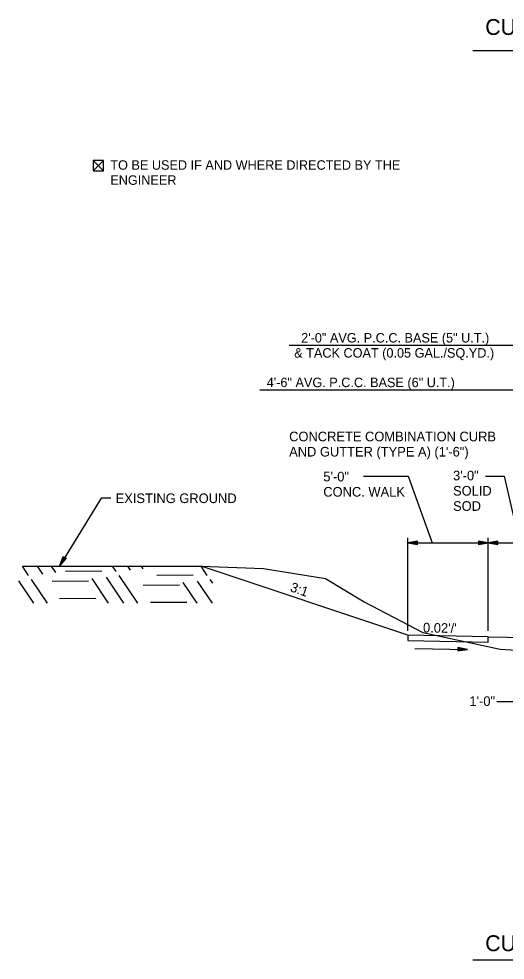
# Model space of a CAD drawing. Extents: x 1001270 to 1003428, y 1840152 to 1842912.
# Drawn here: x 1001294.8 to 1001325.1, y 1841273 to 1841331.7 of the extents above; entities that cross this region are included whole.
import ezdxf

# ---------------------------------------------------------------- set-up
doc = ezdxf.new("R2010")
doc.units = 0
for name, color, linetype in [('10', 7, 'Continuous'), ('19', 7, 'Continuous'), ('20', 7, 'Continuous'), ('8', 7, 'Continuous'), ('Default', 7, 'Continuous')]:
    doc.layers.add(name, color=color, linetype=linetype)

# ---------------------------------------------------------------- blocks, each defined once
blk = doc.blocks.new('TM')
at = {"layer": '8'}
for p, q in [((-120.309, 21.181), (-119.787, -20.829)), ((0, 0), (-120.309, 21.181)), ((-31.382, 2.945), (-120.176, 10.512)), ((-119.787, -20.829), (0, 0)), ((-119.911, -10.826), (-31.307, -3.057))]:
    blk.add_line(p, q, dxfattribs=at)

msp = doc.modelspace()

# ---------------------------------------------------------------- linework, layer by layer
at = {"layer": '10'}
for p, q in [((1001299.414, 1841322.865), (1001300.055, 1841322.224)), ((1001300.055, 1841322.865), (1001299.414, 1841322.224)), ((1001299.795, 1841322.224), (1001299.806, 1841322.224))]:
    msp.add_line(p, q, dxfattribs=at)
msp.add_lwpolyline([(1001299.806, 1841322.224), (1001300.055, 1841322.224), (1001300.055, 1841322.865), (1001299.414, 1841322.865), (1001299.414, 1841322.224), (1001299.795, 1841322.224)], dxfattribs=at)
at = {"layer": '19'}
for p, q in [((1001359.207, 1841329.7), (1001323.061, 1841329.7)), ((1001328.517, 1841311.347), (1001311.62, 1841311.347)), ((1001326.017, 1841308.547), (1001309.801, 1841308.547)), ((1001316.248, 1841303.201), (1001319.04, 1841303.201)), ((1001319.04, 1841303.201), (1001320.535, 1841299.044)), ((1001323.844, 1841303.201), (1001325.022, 1841303.201)), ((1001325.022, 1841303.201), (1001325.979, 1841299.044)), ((1001319.017, 1841293.556), (1001319.017, 1841299.344)), ((1001319.617, 1841299.149), (1001319.017, 1841299.044)), ((1001319.017, 1841299.044), (1001328.517, 1841299.044)), ((1001319.017, 1841299.044), (1001319.617, 1841298.939)), ((1001319.617, 1841299.094), (1001319.177, 1841299.059)), ((1001319.177, 1841299.029), (1001319.617, 1841298.989)), ((1001319.617, 1841298.939), (1001319.617, 1841299.149)), ((1001323.417, 1841299.149), (1001323.417, 1841298.939)), ((1001324.017, 1841299.044), (1001323.417, 1841299.149)), ((1001323.857, 1841299.059), (1001323.417, 1841299.094)), ((1001323.417, 1841298.939), (1001324.017, 1841299.044)), ((1001323.417, 1841298.989), (1001323.857, 1841299.029)), ((1001324.017, 1841293.556), (1001324.017, 1841299.344)), ((1001324.617, 1841299.149), (1001324.017, 1841299.044)), ((1001324.017, 1841299.044), (1001324.617, 1841298.939)), ((1001324.617, 1841299.094), (1001324.177, 1841299.059)), ((1001324.177, 1841299.029), (1001324.617, 1841298.989)), ((1001324.617, 1841298.939), (1001324.617, 1841299.149)), ((1001297.335, 1841297.618), (1001297.558, 1841298.185)), ((1001297.736, 1841298.075), (1001297.335, 1841297.618)), ((1001297.408, 1841297.759), (1001297.601, 1841298.153)), ((1001297.695, 1841298.097), (1001297.431, 1841297.748)), ((1001297.558, 1841298.185), (1001297.736, 1841298.075)), ((1001295.397, 1841297.006), (1001295.017, 1841297.58)), ((1001296.293, 1841297.098), (1001295.961, 1841297.586)), ((1001297.087, 1841297.19), (1001296.826, 1841297.585)), ((1001299.964, 1841297.275), (1001297.703, 1841297.263)), ((1001300.852, 1841297.245), (1001300.626, 1841297.584)), ((1001301.747, 1841297.337), (1001301.581, 1841297.582)), ((1001302.542, 1841297.429), (1001302.436, 1841297.579)), ((1001319.017, 1841293.284), (1001306.135, 1841297.578)), ((1001306.527, 1841296.995), (1001306.135, 1841297.578)), ((1001295.725, 1841295.29), (1001294.788, 1841296.672)), ((1001296.58, 1841295.288), (1001295.583, 1841296.763)), ((1001299.134, 1841296.646), (1001296.863, 1841296.634)), ((1001300.38, 1841295.287), (1001299.347, 1841296.819)), ((1001301.335, 1841295.284), (1001300.243, 1841296.911)), ((1001302.19, 1841295.282), (1001301.037, 1841297.003)), ((1001305.638, 1841297.034), (1001303.379, 1841297.013)), ((1001306.844, 1841295.278), (1001305.918, 1841296.661)), ((1001306.867, 1841296.527), (1001306.713, 1841296.753)), ((1001304.798, 1841296.405), (1001302.539, 1841296.383)), ((1001305.889, 1841295.281), (1001305.023, 1841296.569)), ((1001299.576, 1841295.576), (1001297.316, 1841295.554)), ((1001305.251, 1841295.326), (1001302.981, 1841295.313)), ((1001324.016, 1841293.184), (1001319.017, 1841293.284)), ((1001319.017, 1841293.284), (1001319.017, 1841292.951)), ((1001324.016, 1841293.184), (1001327.017, 1841293.124)), ((1001324.016, 1841292.851), (1001324.016, 1841293.184)), ((1001324.016, 1841293.184), (1001324.016, 1841293.184)), ((1001319.017, 1841292.951), (1001324.016, 1841292.851)), ((1001326.017, 1841289.124), (1001324.569, 1841289.124)), ((1001359.203, 1841273.033), (1001323.057, 1841273.033))]:
    msp.add_line(p, q, dxfattribs=at)
for points in [[(1001300.517, 1841301.817), (1001299.917, 1841301.817), (1001297.335, 1841297.618)], [(1001295.014, 1841297.58), (1001306.135, 1841297.578)], [(1001306.135, 1841297.578), (1001310.023, 1841297.434), (1001313.879, 1841296.811), (1001316.304, 1841295.359), (1001319.957, 1841293.46), (1001324.768, 1841292.421), (1001328.517, 1841292.182), (1001340.782, 1841291.195), (1001352.517, 1841290.374), (1001360.302, 1841289.316), (1001365.338, 1841288.287), (1001370.147, 1841287.7), (1001373.729, 1841287.534)]]:
    msp.add_lwpolyline(points, dxfattribs=at)
at = {"layer": '20'}
msp.add_line((1001319.455, 1841292.465), (1001322.725, 1841292.399), dxfattribs=at)

# ---------------------------------------------------------------- block references
at = {"layer": '19', "xscale": 0.0050063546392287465, "yscale": 0.005006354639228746, "rotation": -1.1310771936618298}
msp.add_blockref('TM', (1001322.725, 1841292.397), dxfattribs=at)

# ---------------------------------------------------------------- texts
at = {"layer": '19'}
for s, height, rotation, p in [('CURB AND GUTTER SUPERELEVATED SECTION', 0.98999, 359.99538, (1001323.84, 1841330.69)), ('CONCRETE COMBINATION CURB', 0.6, 360, (1001311.624, 1841305.368)), ('AND GUTTER (TYPE A) (1\'-6")', 0.6, 360, (1001311.624, 1841304.418)), ('5\'-0"', 0.6, 360, (1001313.751, 1841302.869)), ('3\'-0"', 0.6, 360, (1001321.833, 1841302.933)), ('CONC. WALK', 0.6, 360, (1001313.751, 1841301.919)), ('SOLID ', 0.6, 360, (1001321.833, 1841301.983)), ('SOD', 0.6, 360, (1001321.833, 1841301.033)), ('3:1', 0.6, 340.49426, (1001311.642, 1841296.038)), ("0.02'/'", 0.6, 358.85806, (1001319.957, 1841293.46)), ('1\'-0"', 0.6, 360, (1001322.852, 1841288.877)), ('CURB AND GUTTER SUPERELEVATED SECTION', 0.98999, 359.99538, (1001323.836, 1841273.595))]:
    msp.add_text(s, height=height, rotation=rotation, dxfattribs=at).set_placement(p)
for s, height, p in [('2\'-0" AVG. P.C.C. BASE (5" U.T.)', 0.59001, (1001312.372, 1841311.523)), ('& TACK COAT (0.05 GAL./SQ.YD.)', 0.59001, (1001311.94, 1841310.583)), ('4\'-6" AVG. P.C.C. BASE (6" U.T.)', 0.59001, (1001310.228, 1841308.742)), ('EXISTING GROUND', 0.6, (1001300.817, 1841301.518))]:
    msp.add_text(s, height=height, dxfattribs=at).set_placement(p)
at = {"layer": 'Default'}
for s, height, p in [('TO BE USED IF AND WHERE DIRECTED BY THE ', 0.59001, (1001300.487, 1841322.291)), ('ENGINEER', 0.59, (1001300.486, 1841321.351))]:
    msp.add_text(s, height=height, rotation=359.99538, dxfattribs=at).set_placement(p)

doc.saveas('drawing.dxf')
